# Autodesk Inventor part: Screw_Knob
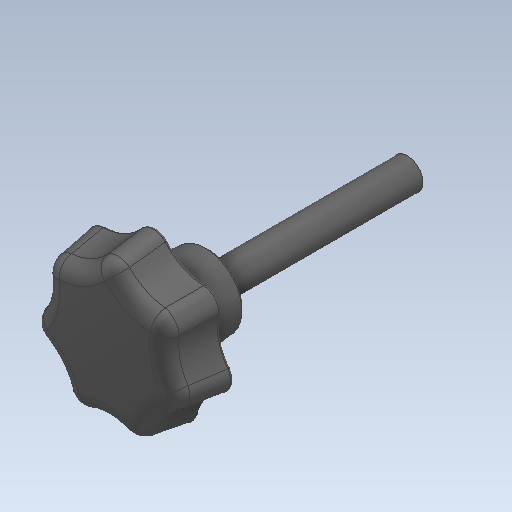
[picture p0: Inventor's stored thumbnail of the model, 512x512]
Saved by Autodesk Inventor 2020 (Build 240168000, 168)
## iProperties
Created: 1900-01
Part Number: Screw_Knob
Material: Générique
Document SubType Name: Modeling
Designer: bruno
Density: 1 g/cm^3
Appearance: Par défaut
Author: bruno
Revision Number: ANYUNSPECIFIED
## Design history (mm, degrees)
feature "Base1"
node "Solide1"
